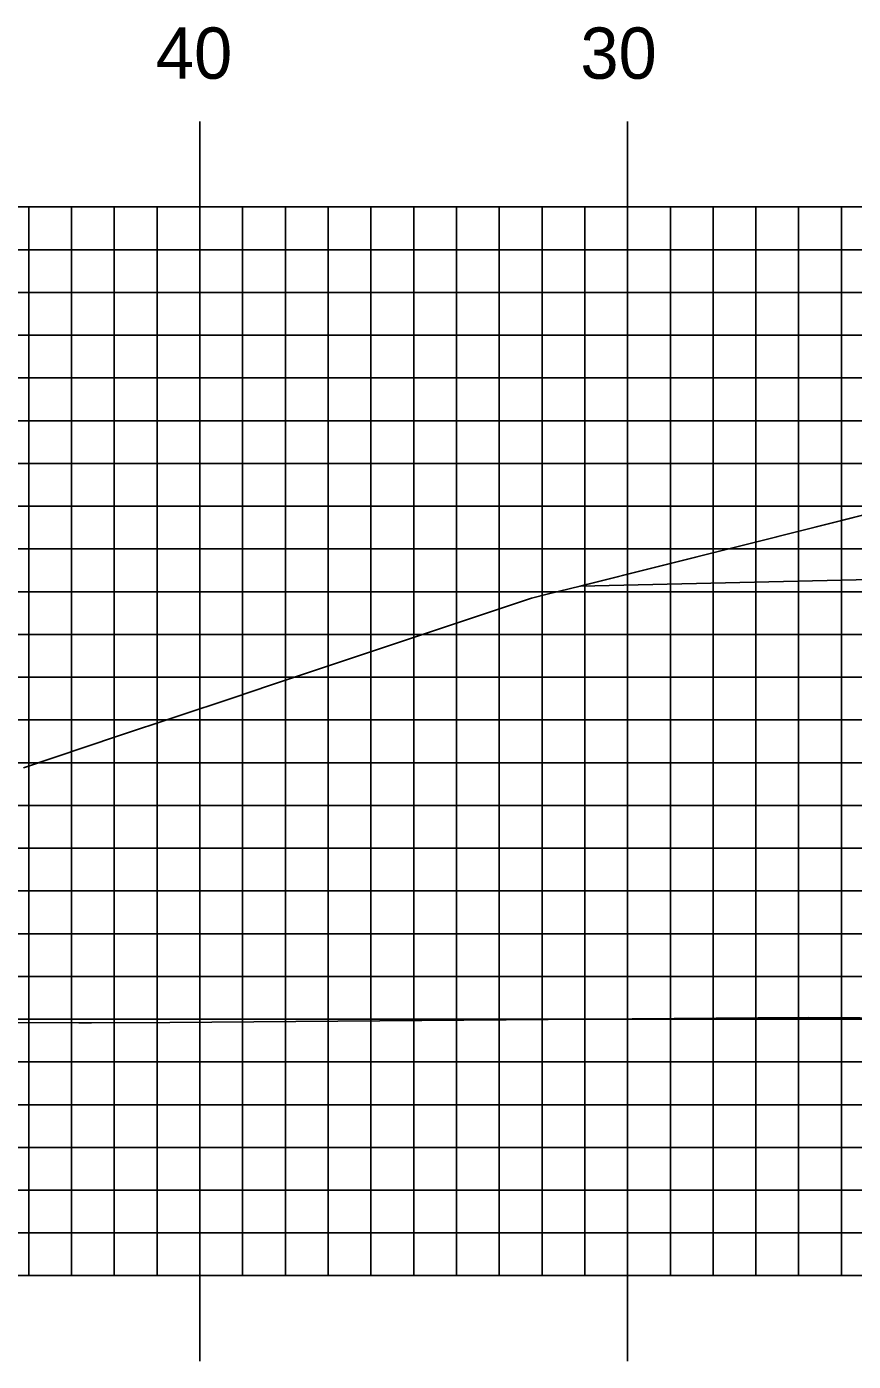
# Model space of a CAD drawing. Extents: x 1814915 to 1815259, y 442591 to 442811.
# Drawn here: x 1815036.97 to 1815056.3, y 442741.66 to 442772.88 of the extents above; entities that cross this region are included whole.
import ezdxf

# ---------------------------------------------------------------- set-up
doc = ezdxf.new("R2010")
doc.units = 0
for name, color, linetype in [('D_Drainage_Culvert', 7, 'Continuous'), ('D_Roadway_Centerline', 7, 'Continuous'), ('D_Roadway_SubGrade', 7, 'Continuous'), ('H_V ANNOTATION', 7, 'Continuous'), ('MAJOR', 7, 'Continuous'), ('MINOR', 7, 'Continuous'), ('S_Roadway_Centerline', 7, 'Continuous')]:
    doc.layers.add(name, color=color, linetype=linetype)

msp = doc.modelspace()

# ---------------------------------------------------------------- linework, layer by layer
at = {"layer": 'D_Drainage_Culvert'}
for p, q in [((1815023.546, 442754.665), (1815135.546, 442754.665)), ((1815023.546, 442748.665), (1815135.546, 442748.665))]:
    msp.add_line(p, q, dxfattribs=at)
at = {"layer": 'D_Roadway_Centerline'}
msp.add_lwpolyline([(1815036.901, 442755.548), (1815039.098, 442756.282), (1815041.826, 442757.192), (1815042.676, 442757.476), (1815047.212, 442758.99), (1815047.469, 442759.076), (1815048.776, 442759.512), (1815049.176, 442759.613), (1815049.915, 442759.798), (1815050.06, 442759.835), (1815050.095, 442759.844), (1815050.124, 442759.851), (1815051.612, 442760.225), (1815054.166, 442760.866), (1815055.775, 442761.27), (1815057.309, 442761.655)], dxfattribs=at)
at = {"layer": 'D_Roadway_SubGrade'}
msp.add_lwpolyline([(1815068.928, 442760.234), (1815049.915, 442759.798), (1815060.867, 442762.549), (1815060.867, 442762.299), (1815068.928, 442762.484), (1815081.021, 442761.992), (1815093.114, 442761.514), (1815101.177, 442761.205), (1815101.177, 442761.455), (1815113.323, 442758.5), (1815093.114, 442759.264), (1815081.021, 442759.742)], close=True, dxfattribs=at)
at = {"layer": 'MAJOR'}
for p, q in [((1815041.021, 442770.669), (1815041.021, 442768.665)), ((1815051.021, 442770.669), (1815051.021, 442768.665)), ((1814941.021, 442768.665), (1815221.021, 442768.665)), ((1814941.021, 442768.665), (1815221.021, 442768.665)), ((1815041.021, 442743.665), (1815041.021, 442768.665)), ((1815051.021, 442743.665), (1815051.021, 442768.665)), ((1814941.021, 442763.665), (1815221.021, 442763.665)), ((1814941.021, 442758.665), (1815221.021, 442758.665)), ((1814941.021, 442753.665), (1815221.021, 442753.665)), ((1814941.021, 442748.665), (1815221.021, 442748.665)), ((1814941.021, 442743.665), (1815221.021, 442743.665)), ((1814941.021, 442743.665), (1815221.021, 442743.665)), ((1815041.021, 442741.661), (1815041.021, 442743.665)), ((1815051.021, 442741.661), (1815051.021, 442743.665))]:
    msp.add_line(p, q, dxfattribs=at)
at = {"layer": 'MINOR'}
for p, q in [((1815037.021, 442743.665), (1815037.021, 442768.665)), ((1815038.021, 442743.665), (1815038.021, 442768.665)), ((1815039.021, 442743.665), (1815039.021, 442768.665)), ((1815040.021, 442743.665), (1815040.021, 442768.665)), ((1815042.021, 442743.665), (1815042.021, 442768.665)), ((1815043.021, 442743.665), (1815043.021, 442768.665)), ((1815044.021, 442743.665), (1815044.021, 442768.665)), ((1815045.021, 442743.665), (1815045.021, 442768.665)), ((1815046.021, 442743.665), (1815046.021, 442768.665)), ((1815047.021, 442743.665), (1815047.021, 442768.665)), ((1815048.021, 442743.665), (1815048.021, 442768.665)), ((1815049.021, 442743.665), (1815049.021, 442768.665)), ((1815050.021, 442743.665), (1815050.021, 442768.665)), ((1815052.021, 442743.665), (1815052.021, 442768.665)), ((1815053.021, 442743.665), (1815053.021, 442768.665)), ((1815054.021, 442743.665), (1815054.021, 442768.665)), ((1815055.021, 442743.665), (1815055.021, 442768.665)), ((1815056.021, 442743.665), (1815056.021, 442768.665)), ((1814941.021, 442767.665), (1815221.021, 442767.665)), ((1814941.021, 442766.665), (1815221.021, 442766.665)), ((1814941.021, 442765.665), (1815221.021, 442765.665)), ((1814941.021, 442764.665), (1815221.021, 442764.665)), ((1814941.021, 442762.665), (1815221.021, 442762.665)), ((1814941.021, 442761.665), (1815221.021, 442761.665)), ((1814941.021, 442760.665), (1815221.021, 442760.665)), ((1814941.021, 442759.665), (1815221.021, 442759.665)), ((1814941.021, 442757.665), (1815221.021, 442757.665)), ((1814941.021, 442756.665), (1815221.021, 442756.665)), ((1814941.021, 442755.665), (1815221.021, 442755.665)), ((1814941.021, 442754.665), (1815221.021, 442754.665)), ((1814941.021, 442752.665), (1815221.021, 442752.665)), ((1814941.021, 442751.665), (1815221.021, 442751.665)), ((1814941.021, 442750.665), (1815221.021, 442750.665)), ((1814941.021, 442749.665), (1815221.021, 442749.665)), ((1814941.021, 442747.665), (1815221.021, 442747.665)), ((1814941.021, 442746.665), (1815221.021, 442746.665)), ((1814941.021, 442745.665), (1815221.021, 442745.665)), ((1814941.021, 442744.665), (1815221.021, 442744.665))]:
    msp.add_line(p, q, dxfattribs=at)
at = {"layer": 'S_Roadway_Centerline'}
msp.add_lwpolyline([(1815005.992, 442749.908), (1815018.998, 442749.725), (1815021.668, 442749.599), (1815038.193, 442749.577), (1815038.357, 442749.576), (1815038.485, 442749.576), (1815040.318, 442749.591), (1815054.077, 442749.699), (1815055.256, 442749.702), (1815070.887, 442749.599), (1815083.088, 442749.849), (1815088.074, 442749.897), (1815095.082, 442749.831), (1815112.583, 442749.662), (1815120.304, 442749.652), (1815126.402, 442749.71), (1815137.574, 442749.683)], dxfattribs=at)

# ---------------------------------------------------------------- texts
at = {"layer": 'H_V ANNOTATION'}
for s, p in [('40', (1815039.993, 442771.665)), ('30', (1815049.918, 442771.665))]:
    msp.add_text(s, height=1.2, dxfattribs=at).set_placement(p)

doc.saveas('drawing.dxf')
